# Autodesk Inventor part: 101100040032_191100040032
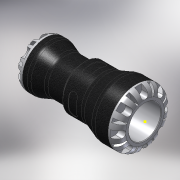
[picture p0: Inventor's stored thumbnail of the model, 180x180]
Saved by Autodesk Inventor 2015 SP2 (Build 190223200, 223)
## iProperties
Created: 2016-12
Part Number: 101100040032_191100040032
Material: PVC-Piping
Description: PLASSON REDUCING COUPLING 40X32 SERIES 1
Document SubType Name: Modeling
Designer: KIM
Mass: 302.001 g
Surface Area: 489.467 cm^2
Volume: 215.715 cm^3
Density: 1.4 g/cm^3
Appearance: Black Cast
Author: KIM
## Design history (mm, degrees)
derived "1011.ipt"
feature "Solid1::1011.ipt"
tag "TaggingFeature1"
body "Solid1"
other parameters: "d0" = 139, "d2" = 29.82, "d5" = 48, "d6" = 71, "d7" = 3.33333, "d8" = 58, "d9" = 32, "d11" = 23.1, "d12" = 55, "d13" = 2.66667, "d14" = 56, "d15" = 46.4, "d16" = 20 deg, "d17" = 20 deg, "d18" = 130 deg, "d22" = 8.8, "d25" = 8.8, "d26" = 0, "d28" = 360 deg, "d30" = 8 deg, "d31" = 0.8, "d32" = 8 deg, "d33" = 0.8, "d35" = 0, "d37" = 360 deg, "d39" = 7.2, "d42" = 7.2, "d43" = 0, "d45" = 360 deg, "d47" = 0.64, "d48" = 8 deg, "d49" = 8 deg, "d50" = 0.64, "d52" = 0, "d54" = 360 deg, "d56" = 11.6, "d57" = 14, "d58" = 0.5, "d60" = 8.4, "d62" = 14.4, "d63" = 0, "d66" = 0, "d68" = 360 deg, "d75" = 10.85912, "d77" = 54.6, "d78" = 0.7, "d1" = 32, "H_" = 139, "l_" = 71, "E1" = 58, "l1" = 55, "Plasson" = 1, "d20" = 9, "d21" = 11, "d24" = 48, "d40" = 58, "d59" = 21.71825
